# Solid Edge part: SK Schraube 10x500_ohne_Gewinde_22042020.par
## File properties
Author: fknapp
Template: Normal.par
Last saved by: fknapp
Revision: 38
Application: Solid Edge
Username: fknapp
Material: Aluminium
Genauigkeit: 0,99
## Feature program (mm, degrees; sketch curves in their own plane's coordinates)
sketch for "unnamed RevolvedProtrusion 1" plane through (0, 0, 0) normal (0, 0, 1) x-axis (1, 0, 0)
  line (0, 54) -> (9, 54)
  line (9, 54) -> (9, 53)
  line (9, 53) -> (5, 49)
  line (5, 49) -> (5, 46.3)
  line (4.5, 42) -> (5, 46.3)
  line (4.5, -433) -> (4.5, 42)
  line (0.5, -446) -> (4.5, -433)
  line (0, -446) -> (0.5, -446)
revolve "unnamed RevolvedProtrusion 1" add full turn 360 deg about sketch line (0, 54) -> (0, -446)
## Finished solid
Body 1: solid body, 8 faces, 7 edges, 0 vertices.
  Faces by surface: cone 3, cylinder 3, plane 2
  Edges by curve: circle 7
Bounding box of the edges (mm): 18.000 x 500.000 x 18.000, from (-9, -446, -9) to (9, 54, 9).
Cylindrical faces by radius (mm): R4.5 x1, R5 x1, R9 x1
Conical faces (half-angle, radius in mm at the cone's reference point): 6.6325 deg R5 x1, 17.1027 deg R4.5 x1, 45 deg R9 x1
Planar faces by outward normal: +y 1, -y 1
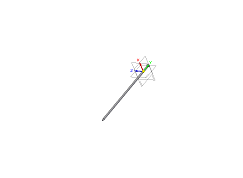
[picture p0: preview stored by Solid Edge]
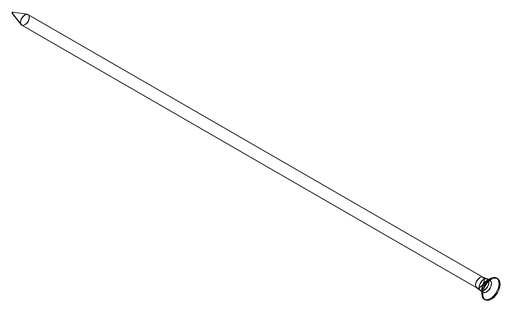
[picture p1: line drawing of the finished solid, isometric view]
